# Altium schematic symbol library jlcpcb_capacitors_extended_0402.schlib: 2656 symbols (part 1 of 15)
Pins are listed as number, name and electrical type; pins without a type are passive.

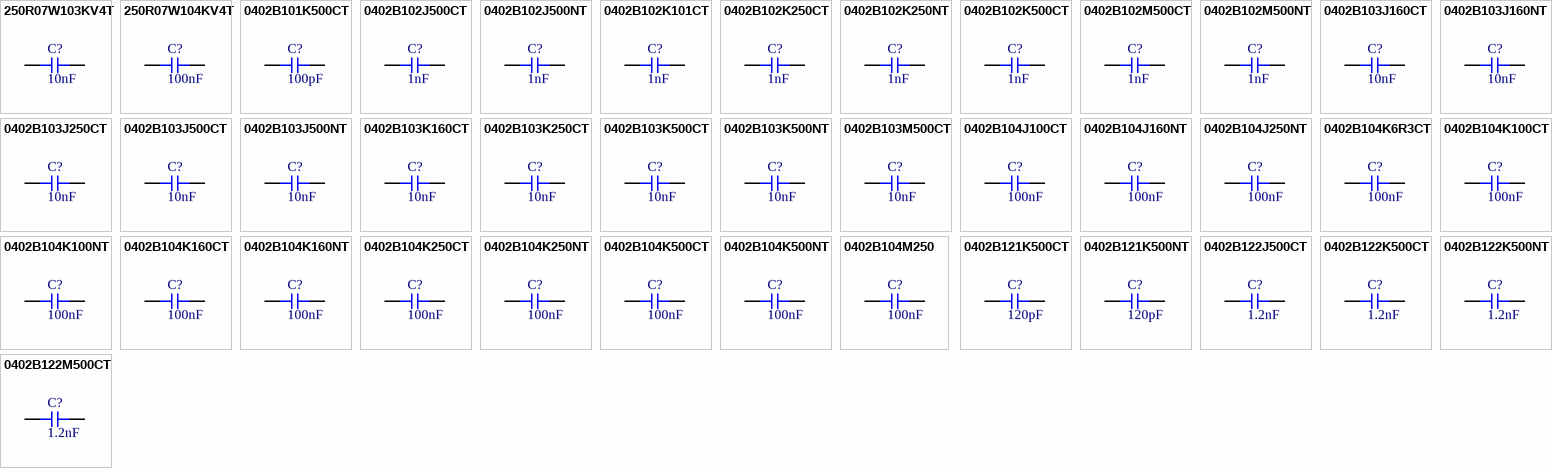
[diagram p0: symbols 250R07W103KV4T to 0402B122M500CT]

## 250R07W103KV4T
designator C?  Capacitance: 10nF  (hidden comment: *)
Capacitor, Ceramic (MLCC), 10nF, ±10%, 25V, X7R, ±10%, SMD 0402; Manufacturer: Johanson Dielectrics; Manufacturer Part Number: 250R07W103KV4T
footprint CAP-0402 (0402 (1005M) Capacitor)
pins: 1, 2

## 250R07W104KV4T
designator C?  Capacitance: 100nF  (hidden comment: *)
Capacitor, Ceramic (MLCC), 100nF, ±10%, 25V, X7R, ±10%, SMD 0402; Manufacturer: Johanson Dielectrics; Manufacturer Part Number: 250R07W104KV4T
footprint CAP-0402 (0402 (1005M) Capacitor)
pins: 1, 2

## 0402B101K500CT
designator C?  Capacitance: 100pF  (hidden comment: *)
Capacitor, Ceramic (MLCC), 100pF, ±10%, 50V, X7R, ±10%, SMD 0402; Manufacturer: Walsin Tech Corp; Manufacturer Part Number: 0402B101K500CT
footprint CAP-0402 (0402 (1005M) Capacitor)
pins: 1, 2

## 0402B102J500CT
designator C?  Capacitance: 1nF  (hidden comment: *)
Capacitor, Ceramic (MLCC), 1nF, ±5%, 50V, X7R, ±5%, SMD 0402; Manufacturer: Walsin Tech Corp; Manufacturer Part Number: 0402B102J500CT
footprint CAP-0402 (0402 (1005M) Capacitor)
pins: 1, 2

## 0402B102J500NT
designator C?  Capacitance: 1nF  (hidden comment: *)
Capacitor, Ceramic (MLCC), 1nF, ±5%, 50V, X7R, ±5%, SMD 0402; Manufacturer: FH(Guangdong Fenghua Advanced Tech); Manufacturer Part Number: 0402B102J500NT
footprint CAP-0402 (0402 (1005M) Capacitor)
pins: 1, 2

## 0402B102K101CT
designator C?  Capacitance: 1nF  (hidden comment: *)
Capacitor, Ceramic (MLCC), 1nF, ±10%, 100V, X7R, ±10%, SMD 0402; Manufacturer: Walsin Tech Corp; Manufacturer Part Number: 0402B102K101CT
footprint CAP-0402 (0402 (1005M) Capacitor)
pins: 1, 2

## 0402B102K250CT
designator C?  Capacitance: 1nF  (hidden comment: *)
Capacitor, Ceramic (MLCC), 1nF, ±10%, 25V, X7R, ±10%, SMD 0402; Manufacturer: Walsin Tech Corp; Manufacturer Part Number: 0402B102K250CT
footprint CAP-0402 (0402 (1005M) Capacitor)
pins: 1, 2

## 0402B102K250NT
designator C?  Capacitance: 1nF  (hidden comment: *)
Capacitor, Ceramic (MLCC), 1nF, ±10%, 25V, X7R, ±10%, SMD 0402; Manufacturer: FH(Guangdong Fenghua Advanced Tech); Manufacturer Part Number: 0402B102K250NT
footprint CAP-0402 (0402 (1005M) Capacitor)
pins: 1, 2

## 0402B102K500CT
designator C?  Capacitance: 1nF  (hidden comment: *)
Capacitor, Ceramic (MLCC), 1nF, ±10%, 50V, X7R, ±10%, SMD 0402; Manufacturer: Walsin Tech Corp; Manufacturer Part Number: 0402B102K500CT
footprint CAP-0402 (0402 (1005M) Capacitor)
pins: 1, 2

## 0402B102M500CT
designator C?  Capacitance: 1nF  (hidden comment: *)
Capacitor, Ceramic (MLCC), 1nF, ±20%, 50V, X7R, ±20%, SMD 0402; Manufacturer: Walsin Tech Corp; Manufacturer Part Number: 0402B102M500CT
footprint CAP-0402 (0402 (1005M) Capacitor)
pins: 1, 2

## 0402B102M500NT
designator C?  Capacitance: 1nF  (hidden comment: *)
Capacitor, Ceramic (MLCC), 1nF, ±20%, 50V, X7R, ±20%, SMD 0402; Manufacturer: FH(Guangdong Fenghua Advanced Tech); Manufacturer Part Number: 0402B102M500NT
footprint CAP-0402 (0402 (1005M) Capacitor)
pins: 1, 2

## 0402B103J160CT
designator C?  Capacitance: 10nF  (hidden comment: *)
Capacitor, Ceramic (MLCC), 10nF, ±5%, 16V, X7R, ±5%, SMD 0402; Manufacturer: Walsin Tech Corp; Manufacturer Part Number: 0402B103J160CT
footprint CAP-0402 (0402 (1005M) Capacitor)
pins: 1, 2

## 0402B103J160NT
designator C?  Capacitance: 10nF  (hidden comment: *)
Capacitor, Ceramic (MLCC), 10nF, ±5%, 16V, ±5%, SMD 0402; Manufacturer: FH (Guangdong Fenghua Advanced Tech); Manufacturer Part Number: 0402B103J160NT
footprint CAP-0402 (0402 (1005M) Capacitor)
pins: 1, 2

## 0402B103J250CT
designator C?  Capacitance: 10nF  (hidden comment: *)
Capacitor, Ceramic (MLCC), 10nF, ±5%, 25V, X7R, ±5%, SMD 0402; Manufacturer: Walsin Tech Corp; Manufacturer Part Number: 0402B103J250CT
footprint CAP-0402 (0402 (1005M) Capacitor)
pins: 1, 2

## 0402B103J500CT
designator C?  Capacitance: 10nF  (hidden comment: *)
Capacitor, Ceramic (MLCC), 10nF, ±5%, 50V, X7R, ±5%, SMD 0402; Manufacturer: Walsin Tech Corp; Manufacturer Part Number: 0402B103J500CT
footprint CAP-0402 (0402 (1005M) Capacitor)
pins: 1, 2

## 0402B103J500NT
designator C?  Capacitance: 10nF  (hidden comment: *)
Capacitor, Ceramic (MLCC), 10nF, ±5%, 50V, ±5%, SMD 0402; Manufacturer: FH (Guangdong Fenghua Advanced Tech); Manufacturer Part Number: 0402B103J500NT
footprint CAP-0402 (0402 (1005M) Capacitor)
pins: 1, 2

## 0402B103K160CT
designator C?  Capacitance: 10nF  (hidden comment: *)
Capacitor, Ceramic (MLCC), 10nF, ±10%, 16V, X7R, ±10%, SMD 0402; Manufacturer: Walsin Tech Corp; Manufacturer Part Number: 0402B103K160CT
footprint CAP-0402 (0402 (1005M) Capacitor)
pins: 1, 2

## 0402B103K250CT
designator C?  Capacitance: 10nF  (hidden comment: *)
Capacitor, Ceramic (MLCC), 10nF, ±10%, 25V, X7R, ±10%, SMD 0402; Manufacturer: Walsin Tech Corp; Manufacturer Part Number: 0402B103K250CT
footprint CAP-0402 (0402 (1005M) Capacitor)
pins: 1, 2

## 0402B103K500CT
designator C?  Capacitance: 10nF  (hidden comment: *)
Capacitor, Ceramic (MLCC), 10nF, ±10%, 50V, X7R, ±10%, SMD 0402; Manufacturer: Walsin Tech Corp; Manufacturer Part Number: 0402B103K500CT
footprint CAP-0402 (0402 (1005M) Capacitor)
pins: 1, 2

## 0402B103K500NT
designator C?  Capacitance: 10nF  (hidden comment: *)
Capacitor, Ceramic (MLCC), 10nF, ±10%, 50V, X7R, ±10%, SMD 0402; Manufacturer: FH(Guangdong Fenghua Advanced Tech); Manufacturer Part Number: 0402B103K500NT
footprint CAP-0402 (0402 (1005M) Capacitor)
pins: 1, 2

## 0402B103M500CT
designator C?  Capacitance: 10nF  (hidden comment: *)
Capacitor, Ceramic (MLCC), 10nF, ±20%, 50V, X7R, ±20%, SMD 0402; Manufacturer: Walsin Tech Corp; Manufacturer Part Number: 0402B103M500CT
footprint CAP-0402 (0402 (1005M) Capacitor)
pins: 1, 2

## 0402B104J100CT
designator C?  Capacitance: 100nF  (hidden comment: *)
Capacitor, Ceramic (MLCC), 100nF, ±5%, 10V, X7R, ±5%, SMD 0402; Manufacturer: Walsin Tech Corp; Manufacturer Part Number: 0402B104J100CT
footprint CAP-0402 (0402 (1005M) Capacitor)
pins: 1, 2

## 0402B104J160NT
designator C?  Capacitance: 100nF  (hidden comment: *)
Capacitor, Ceramic (MLCC), 100nF, ±5%, 16V, X7R, ±5%, SMD 0402; Manufacturer: FH(Guangdong Fenghua Advanced Tech); Manufacturer Part Number: 0402B104J160NT
footprint CAP-0402 (0402 (1005M) Capacitor)
pins: 1, 2

## 0402B104J250NT
designator C?  Capacitance: 100nF  (hidden comment: *)
Capacitor, Ceramic (MLCC), 100nF, ±5%, 25V, X7R, ±5%, SMD 0402; Manufacturer: FH(Guangdong Fenghua Advanced Tech); Manufacturer Part Number: 0402B104J250NT
footprint CAP-0402 (0402 (1005M) Capacitor)
pins: 1, 2

## 0402B104K6R3CT
designator C?  Capacitance: 100nF  (hidden comment: *)
Capacitor, Ceramic (MLCC), 100nF, ±10%, 6.3V, X7R, ±10%, SMD 0402; Manufacturer: Walsin Tech Corp; Manufacturer Part Number: 0402B104K6R3CT
footprint CAP-0402 (0402 (1005M) Capacitor)
pins: 1, 2

## 0402B104K100CT
designator C?  Capacitance: 100nF  (hidden comment: *)
Capacitor, Ceramic (MLCC), 100nF, ±10%, 10V, X7R, ±10%, SMD 0402; Manufacturer: Walsin Tech Corp; Manufacturer Part Number: 0402B104K100CT
footprint CAP-0402 (0402 (1005M) Capacitor)
pins: 1, 2

## 0402B104K100NT
designator C?  Capacitance: 100nF  (hidden comment: *)
Capacitor, Ceramic (MLCC), 100nF, ±10%, 10V, X7R, ±10%, SMD 0402; Manufacturer: FH(Guangdong Fenghua Advanced Tech); Manufacturer Part Number: 0402B104K100NT
footprint CAP-0402 (0402 (1005M) Capacitor)
pins: 1, 2

## 0402B104K160CT
designator C?  Capacitance: 100nF  (hidden comment: *)
Capacitor, Ceramic (MLCC), 100nF, ±10%, 16V, X7R, ±10%, SMD 0402; Manufacturer: Walsin Tech Corp; Manufacturer Part Number: 0402B104K160CT
footprint CAP-0402 (0402 (1005M) Capacitor)
pins: 1, 2

## 0402B104K160NT
designator C?  Capacitance: 100nF  (hidden comment: *)
Capacitor, Ceramic (MLCC), 100nF, ±10%, 16V, X7R, ±10%, SMD 0402; Manufacturer: FH(Guangdong Fenghua Advanced Tech); Manufacturer Part Number: 0402B104K160NT
footprint CAP-0402 (0402 (1005M) Capacitor)
pins: 1, 2

## 0402B104K250CT
designator C?  Capacitance: 100nF  (hidden comment: *)
Capacitor, Ceramic (MLCC), 100nF, ±10%, 25V, X7R, ±10%, SMD 0402; Manufacturer: Walsin Tech Corp; Manufacturer Part Number: 0402B104K250CT
footprint CAP-0402 (0402 (1005M) Capacitor)
pins: 1, 2

## 0402B104K250NT
designator C?  Capacitance: 100nF  (hidden comment: *)
Capacitor, Ceramic (MLCC), 100nF, ±10%, 25V, X7R, ±10%, SMD 0402; Manufacturer: FH(Guangdong Fenghua Advanced Tech); Manufacturer Part Number: 0402B104K250NT
footprint CAP-0402 (0402 (1005M) Capacitor)
pins: 1, 2

## 0402B104K500CT
designator C?  Capacitance: 100nF  (hidden comment: *)
Capacitor, Ceramic (MLCC), 100nF, ±10%, 50V, X7R, ±10%, SMD 0402; Manufacturer: Walsin Tech Corp; Manufacturer Part Number: 0402B104K500CT
footprint CAP-0402 (0402 (1005M) Capacitor)
pins: 1, 2

## 0402B104K500NT
designator C?  Capacitance: 100nF  (hidden comment: *)
Capacitor, Ceramic (MLCC), 100nF, ±10%, 50V, X7R, ±10%, SMD 0402; Manufacturer: FH(Guangdong Fenghua Advanced Tech); Manufacturer Part Number: 0402B104K500NT
footprint CAP-0402 (0402 (1005M) Capacitor)
pins: 1, 2

## 0402B104M250
designator C?  Capacitance: 100nF  (hidden comment: *)
Capacitor, Ceramic (MLCC), 100nF, ±20%, 25V, X7R, ±20%, SMD 0402; Manufacturer: Walsin Tech Corp; Manufacturer Part Number: 0402B104M250
footprint CAP-0402 (0402 (1005M) Capacitor)
pins: 1, 2

## 0402B121K500CT
designator C?  Capacitance: 120pF  (hidden comment: *)
Capacitor, Ceramic (MLCC), 120pF, ±10%, 50V, X7R, ±10%, SMD 0402; Manufacturer: Walsin Tech Corp; Manufacturer Part Number: 0402B121K500CT
footprint CAP-0402 (0402 (1005M) Capacitor)
pins: 1, 2

## 0402B121K500NT
designator C?  Capacitance: 120pF  (hidden comment: *)
Capacitor, Ceramic (MLCC), 120pF, ±10%, 50V, X7R, ±10%, SMD 0402; Manufacturer: FH(Guangdong Fenghua Advanced Tech); Manufacturer Part Number: 0402B121K500NT
footprint CAP-0402 (0402 (1005M) Capacitor)
pins: 1, 2

## 0402B122J500CT
designator C?  Capacitance: 1.2nF  (hidden comment: *)
Capacitor, Ceramic (MLCC), 1.2nF, ±5%, 50V, X7R, ±5%, SMD 0402; Manufacturer: Walsin Tech Corp; Manufacturer Part Number: 0402B122J500CT
footprint CAP-0402 (0402 (1005M) Capacitor)
pins: 1, 2

## 0402B122K500CT
designator C?  Capacitance: 1.2nF  (hidden comment: *)
Capacitor, Ceramic (MLCC), 1.2nF, ±10%, 50V, X7R, ±10%, SMD 0402; Manufacturer: Walsin Tech Corp; Manufacturer Part Number: 0402B122K500CT
footprint CAP-0402 (0402 (1005M) Capacitor)
pins: 1, 2

## 0402B122K500NT
designator C?  Capacitance: 1.2nF  (hidden comment: *)
Capacitor, Ceramic (MLCC), 1.2nF, ±10%, 50V, X7R, ±10%, SMD 0402; Manufacturer: FH(Guangdong Fenghua Advanced Tech); Manufacturer Part Number: 0402B122K500NT
footprint CAP-0402 (0402 (1005M) Capacitor)
pins: 1, 2

## 0402B122M500CT
designator C?  Capacitance: 1.2nF  (hidden comment: *)
Capacitor, Ceramic (MLCC), 1.2nF, ±20%, 50V, X7R, ±20%, SMD 0402; Manufacturer: Walsin Tech Corp; Manufacturer Part Number: 0402B122M500CT
footprint CAP-0402 (0402 (1005M) Capacitor)
pins: 1, 2

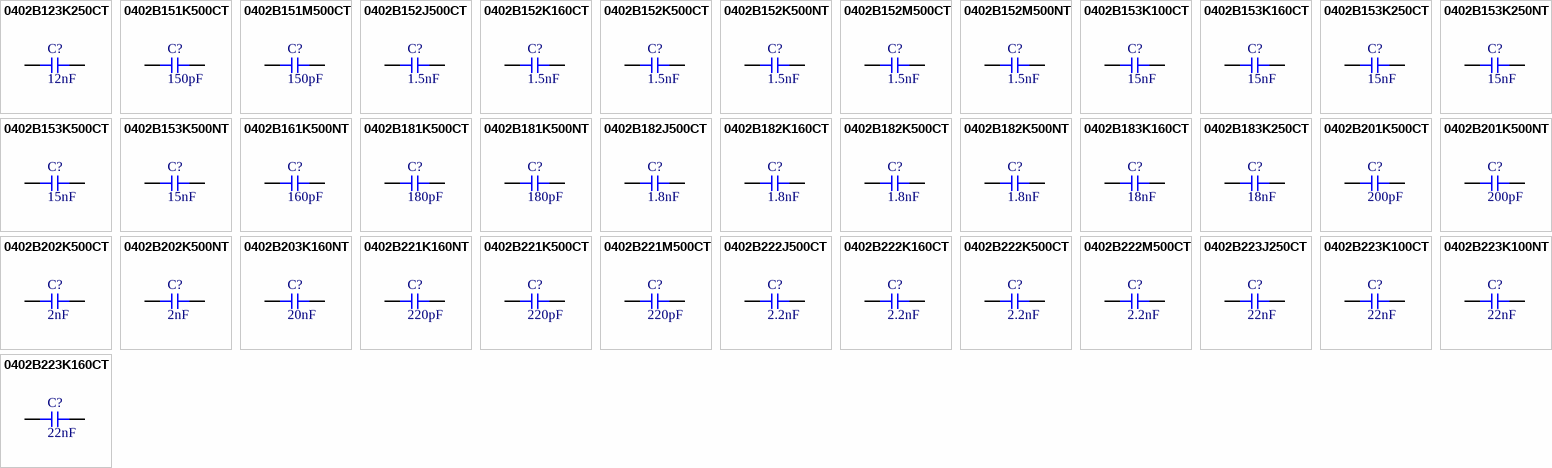
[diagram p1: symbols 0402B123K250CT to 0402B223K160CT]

## 0402B123K250CT
designator C?  Capacitance: 12nF  (hidden comment: *)
Capacitor, Ceramic (MLCC), 12nF, ±10%, 25V, X7R, ±10%, SMD 0402; Manufacturer: Walsin Tech Corp; Manufacturer Part Number: 0402B123K250CT
footprint CAP-0402 (0402 (1005M) Capacitor)
pins: 1, 2

## 0402B151K500CT
designator C?  Capacitance: 150pF  (hidden comment: *)
Capacitor, Ceramic (MLCC), 150pF, ±10%, 50V, X7R, ±10%, SMD 0402; Manufacturer: Walsin Tech Corp; Manufacturer Part Number: 0402B151K500CT
footprint CAP-0402 (0402 (1005M) Capacitor)
pins: 1, 2

## 0402B151M500CT
designator C?  Capacitance: 150pF  (hidden comment: *)
Capacitor, Ceramic (MLCC), 150pF, ±20%, 50V, X7R, ±20%, SMD 0402; Manufacturer: Walsin Tech Corp; Manufacturer Part Number: 0402B151M500CT
footprint CAP-0402 (0402 (1005M) Capacitor)
pins: 1, 2

## 0402B152J500CT
designator C?  Capacitance: 1.5nF  (hidden comment: *)
Capacitor, Ceramic (MLCC), 1.5nF, ±5%, 50V, X7R, ±5%, SMD 0402; Manufacturer: Walsin Tech Corp; Manufacturer Part Number: 0402B152J500CT
footprint CAP-0402 (0402 (1005M) Capacitor)
pins: 1, 2

## 0402B152K160CT
designator C?  Capacitance: 1.5nF  (hidden comment: *)
Capacitor, Ceramic (MLCC), 1.5nF, ±10%, 16V, X7R, ±10%, SMD 0402; Manufacturer: Walsin Tech Corp; Manufacturer Part Number: 0402B152K160CT
footprint CAP-0402 (0402 (1005M) Capacitor)
pins: 1, 2

## 0402B152K500CT
designator C?  Capacitance: 1.5nF  (hidden comment: *)
Capacitor, Ceramic (MLCC), 1.5nF, ±10%, 50V, X7R, ±10%, SMD 0402; Manufacturer: Walsin Tech Corp; Manufacturer Part Number: 0402B152K500CT
footprint CAP-0402 (0402 (1005M) Capacitor)
pins: 1, 2

## 0402B152K500NT
designator C?  Capacitance: 1.5nF  (hidden comment: *)
Capacitor, Ceramic (MLCC), 1.5nF, ±10%, 50V, X7R, ±10%, SMD 0402; Manufacturer: FH(Guangdong Fenghua Advanced Tech); Manufacturer Part Number: 0402B152K500NT
footprint CAP-0402 (0402 (1005M) Capacitor)
pins: 1, 2

## 0402B152M500CT
designator C?  Capacitance: 1.5nF  (hidden comment: *)
Capacitor, Ceramic (MLCC), 1.5nF, ±20%, 50V, X7R, ±20%, SMD 0402; Manufacturer: Walsin Tech Corp; Manufacturer Part Number: 0402B152M500CT
footprint CAP-0402 (0402 (1005M) Capacitor)
pins: 1, 2

## 0402B152M500NT
designator C?  Capacitance: 1.5nF  (hidden comment: *)
Capacitor, Ceramic (MLCC), 1.5nF, ±20%, 50V, X7R, ±20%, SMD 0402; Manufacturer: FH(Guangdong Fenghua Advanced Tech); Manufacturer Part Number: 0402B152M500NT
footprint CAP-0402 (0402 (1005M) Capacitor)
pins: 1, 2

## 0402B153K100CT
designator C?  Capacitance: 15nF  (hidden comment: *)
Capacitor, Ceramic (MLCC), 15nF, ±10%, 10V, X7R, ±10%, SMD 0402; Manufacturer: Walsin Tech Corp; Manufacturer Part Number: 0402B153K100CT
footprint CAP-0402 (0402 (1005M) Capacitor)
pins: 1, 2

## 0402B153K160CT
designator C?  Capacitance: 15nF  (hidden comment: *)
Capacitor, Ceramic (MLCC), 15nF, ±10%, 16V, X7R, ±10%, SMD 0402; Manufacturer: Walsin Tech Corp; Manufacturer Part Number: 0402B153K160CT
footprint CAP-0402 (0402 (1005M) Capacitor)
pins: 1, 2

## 0402B153K250CT
designator C?  Capacitance: 15nF  (hidden comment: *)
Capacitor, Ceramic (MLCC), 15nF, ±10%, 25V, X7R, ±10%, SMD 0402; Manufacturer: Walsin Tech Corp; Manufacturer Part Number: 0402B153K250CT
footprint CAP-0402 (0402 (1005M) Capacitor)
pins: 1, 2

## 0402B153K250NT
designator C?  Capacitance: 15nF  (hidden comment: *)
Capacitor, Ceramic (MLCC), 15nF, ±10%, 25V, X7R, ±10%, SMD 0402; Manufacturer: FH(Guangdong Fenghua Advanced Tech); Manufacturer Part Number: 0402B153K250NT
footprint CAP-0402 (0402 (1005M) Capacitor)
pins: 1, 2

## 0402B153K500CT
designator C?  Capacitance: 15nF  (hidden comment: *)
Capacitor, Ceramic (MLCC), 15nF, ±10%, 50V, X7R, ±10%, SMD 0402; Manufacturer: Walsin Tech Corp; Manufacturer Part Number: 0402B153K500CT
footprint CAP-0402 (0402 (1005M) Capacitor)
pins: 1, 2

## 0402B153K500NT
designator C?  Capacitance: 15nF  (hidden comment: *)
Capacitor, Ceramic (MLCC), 15nF, ±10%, 50V, X7R, ±10%, SMD 0402; Manufacturer: FH(Guangdong Fenghua Advanced Tech); Manufacturer Part Number: 0402B153K500NT
footprint CAP-0402 (0402 (1005M) Capacitor)
pins: 1, 2

## 0402B161K500NT
designator C?  Capacitance: 160pF  (hidden comment: *)
Capacitor, Ceramic (MLCC), 160pF, ±10%, 50V, X7R, ±10%, SMD 0402; Manufacturer: FH(Guangdong Fenghua Advanced Tech); Manufacturer Part Number: 0402B161K500NT
footprint CAP-0402 (0402 (1005M) Capacitor)
pins: 1, 2

## 0402B181K500CT
designator C?  Capacitance: 180pF  (hidden comment: *)
Capacitor, Ceramic (MLCC), 180pF, ±10%, 50V, X7R, ±10%, SMD 0402; Manufacturer: Walsin Tech Corp; Manufacturer Part Number: 0402B181K500CT
footprint CAP-0402 (0402 (1005M) Capacitor)
pins: 1, 2

## 0402B181K500NT
designator C?  Capacitance: 180pF  (hidden comment: *)
Capacitor, Ceramic (MLCC), 180pF, ±10%, 50V, X7R, ±10%, SMD 0402; Manufacturer: FH(Guangdong Fenghua Advanced Tech); Manufacturer Part Number: 0402B181K500NT
footprint CAP-0402 (0402 (1005M) Capacitor)
pins: 1, 2

## 0402B182J500CT
designator C?  Capacitance: 1.8nF  (hidden comment: *)
Capacitor, Ceramic (MLCC), 1.8nF, ±5%, 50V, X7R, ±5%, SMD 0402; Manufacturer: Walsin Tech Corp; Manufacturer Part Number: 0402B182J500CT
footprint CAP-0402 (0402 (1005M) Capacitor)
pins: 1, 2

## 0402B182K160CT
designator C?  Capacitance: 1.8nF  (hidden comment: *)
Capacitor, Ceramic (MLCC), 1.8nF, ±10%, 16V, X7R, ±10%, SMD 0402; Manufacturer: Walsin Tech Corp; Manufacturer Part Number: 0402B182K160CT
footprint CAP-0402 (0402 (1005M) Capacitor)
pins: 1, 2

## 0402B182K500CT
designator C?  Capacitance: 1.8nF  (hidden comment: *)
Capacitor, Ceramic (MLCC), 1.8nF, ±10%, 50V, X7R, ±10%, SMD 0402; Manufacturer: Walsin Tech Corp; Manufacturer Part Number: 0402B182K500CT
footprint CAP-0402 (0402 (1005M) Capacitor)
pins: 1, 2

## 0402B182K500NT
designator C?  Capacitance: 1.8nF  (hidden comment: *)
Capacitor, Ceramic (MLCC), 1.8nF, ±10%, 50V, X7R, ±10%, SMD 0402; Manufacturer: FH(Guangdong Fenghua Advanced Tech); Manufacturer Part Number: 0402B182K500NT
footprint CAP-0402 (0402 (1005M) Capacitor)
pins: 1, 2

## 0402B183K160CT
designator C?  Capacitance: 18nF  (hidden comment: *)
Capacitor, Ceramic (MLCC), 18nF, ±10%, 16V, X7R, ±10%, SMD 0402; Manufacturer: Walsin Tech Corp; Manufacturer Part Number: 0402B183K160CT
footprint CAP-0402 (0402 (1005M) Capacitor)
pins: 1, 2

## 0402B183K250CT
designator C?  Capacitance: 18nF  (hidden comment: *)
Capacitor, Ceramic (MLCC), 18nF, ±10%, 25V, X7R, ±10%, SMD 0402; Manufacturer: Walsin Tech Corp; Manufacturer Part Number: 0402B183K250CT
footprint CAP-0402 (0402 (1005M) Capacitor)
pins: 1, 2

## 0402B201K500CT
designator C?  Capacitance: 200pF  (hidden comment: *)
Capacitor, Ceramic (MLCC), 200pF, ±10%, 50V, X7R, ±10%, SMD 0402; Manufacturer: Walsin Tech Corp; Manufacturer Part Number: 0402B201K500CT
footprint CAP-0402 (0402 (1005M) Capacitor)
pins: 1, 2

## 0402B201K500NT
designator C?  Capacitance: 200pF  (hidden comment: *)
Capacitor, Ceramic (MLCC), 200pF, ±10%, 50V, X7R, ±10%, SMD 0402; Manufacturer: FH(Guangdong Fenghua Advanced Tech); Manufacturer Part Number: 0402B201K500NT
footprint CAP-0402 (0402 (1005M) Capacitor)
pins: 1, 2

## 0402B202K500CT
designator C?  Capacitance: 2nF  (hidden comment: *)
Capacitor, Ceramic (MLCC), 2nF, ±10%, 50V, X7R, ±10%, SMD 0402; Manufacturer: Walsin Tech Corp; Manufacturer Part Number: 0402B202K500CT
footprint CAP-0402 (0402 (1005M) Capacitor)
pins: 1, 2

## 0402B202K500NT
designator C?  Capacitance: 2nF  (hidden comment: *)
Capacitor, Ceramic (MLCC), 2nF, ±10%, 50V, ±10%, SMD 0402; Manufacturer: FH(Guangdong Fenghua Advanced Tech); Manufacturer Part Number: 0402B202K500NT
footprint CAP-0402 (0402 (1005M) Capacitor)
pins: 1, 2

## 0402B203K160NT
designator C?  Capacitance: 20nF  (hidden comment: *)
Capacitor, Ceramic (MLCC), 20nF, ±10%, 16V, ±10%, SMD 0402; Manufacturer: FH(Guangdong Fenghua Advanced Tech); Manufacturer Part Number: 0402B203K160NT
footprint CAP-0402 (0402 (1005M) Capacitor)
pins: 1, 2

## 0402B221K160NT
designator C?  Capacitance: 220pF  (hidden comment: *)
Capacitor, Ceramic (MLCC), 220pF, ±10%, 16V, X7R, ±10%, SMD 0402; Manufacturer: FH(Guangdong Fenghua Advanced Tech); Manufacturer Part Number: 0402B221K160NT
footprint CAP-0402 (0402 (1005M) Capacitor)
pins: 1, 2

## 0402B221K500CT
designator C?  Capacitance: 220pF  (hidden comment: *)
Capacitor, Ceramic (MLCC), 220pF, ±10%, 50V, X7R, ±10%, SMD 0402; Manufacturer: Walsin Tech Corp; Manufacturer Part Number: 0402B221K500CT
footprint CAP-0402 (0402 (1005M) Capacitor)
pins: 1, 2

## 0402B221M500CT
designator C?  Capacitance: 220pF  (hidden comment: *)
Capacitor, Ceramic (MLCC), 220pF, ±20%, 50V, X7R, ±20%, SMD 0402; Manufacturer: Walsin Tech Corp; Manufacturer Part Number: 0402B221M500CT
footprint CAP-0402 (0402 (1005M) Capacitor)
pins: 1, 2

## 0402B222J500CT
designator C?  Capacitance: 2.2nF  (hidden comment: *)
Capacitor, Ceramic (MLCC), 2.2nF, ±5%, 50V, X7R, ±5%, SMD 0402; Manufacturer: Walsin Tech Corp; Manufacturer Part Number: 0402B222J500CT
footprint CAP-0402 (0402 (1005M) Capacitor)
pins: 1, 2

## 0402B222K160CT
designator C?  Capacitance: 2.2nF  (hidden comment: *)
Capacitor, Ceramic (MLCC), 2.2nF, ±10%, 16V, X7R, ±10%, SMD 0402; Manufacturer: Walsin Tech Corp; Manufacturer Part Number: 0402B222K160CT
footprint CAP-0402 (0402 (1005M) Capacitor)
pins: 1, 2

## 0402B222K500CT
designator C?  Capacitance: 2.2nF  (hidden comment: *)
Capacitor, Ceramic (MLCC), 2.2nF, ±10%, 50V, X7R, ±10%, SMD 0402; Manufacturer: Walsin Tech Corp; Manufacturer Part Number: 0402B222K500CT
footprint CAP-0402 (0402 (1005M) Capacitor)
pins: 1, 2

## 0402B222M500CT
designator C?  Capacitance: 2.2nF  (hidden comment: *)
Capacitor, Ceramic (MLCC), 2.2nF, ±20%, 50V, X7R, ±20%, SMD 0402; Manufacturer: Walsin Tech Corp; Manufacturer Part Number: 0402B222M500CT
footprint CAP-0402 (0402 (1005M) Capacitor)
pins: 1, 2

## 0402B223J250CT
designator C?  Capacitance: 22nF  (hidden comment: *)
Capacitor, Ceramic (MLCC), 22nF, ±5%, 25V, X7R, ±5%, SMD 0402; Manufacturer: Walsin Tech Corp; Manufacturer Part Number: 0402B223J250CT
footprint CAP-0402 (0402 (1005M) Capacitor)
pins: 1, 2

## 0402B223K100CT
designator C?  Capacitance: 22nF  (hidden comment: *)
Capacitor, Ceramic (MLCC), 22nF, ±10%, 10V, X7R, ±10%, SMD 0402; Manufacturer: Walsin Tech Corp; Manufacturer Part Number: 0402B223K100CT
footprint CAP-0402 (0402 (1005M) Capacitor)
pins: 1, 2

## 0402B223K100NT
designator C?  Capacitance: 22nF  (hidden comment: *)
Capacitor, Ceramic (MLCC), 22nF, ±10%, 10V, X7R, ±10%, SMD 0402; Manufacturer: FH(Guangdong Fenghua Advanced Tech); Manufacturer Part Number: 0402B223K100NT
footprint CAP-0402 (0402 (1005M) Capacitor)
pins: 1, 2

## 0402B223K160CT
designator C?  Capacitance: 22nF  (hidden comment: *)
Capacitor, Ceramic (MLCC), 22nF, ±10%, 16V, X7R, ±10%, SMD 0402; Manufacturer: Walsin Tech Corp; Manufacturer Part Number: 0402B223K160CT
footprint CAP-0402 (0402 (1005M) Capacitor)
pins: 1, 2

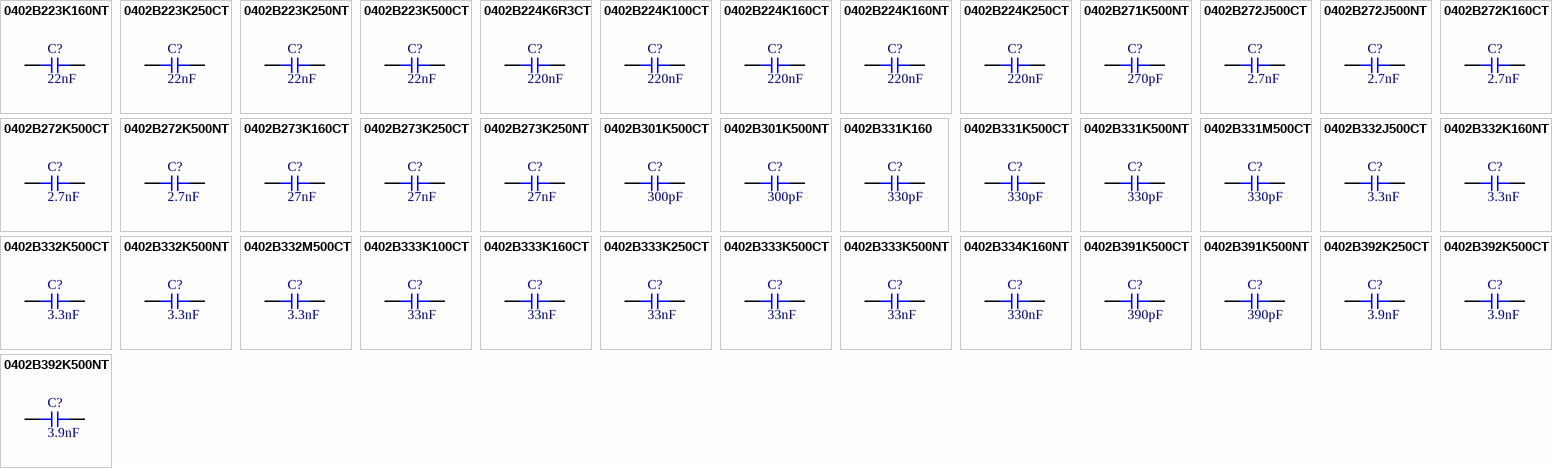
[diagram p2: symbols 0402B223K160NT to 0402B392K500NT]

## 0402B223K160NT
designator C?  Capacitance: 22nF  (hidden comment: *)
Capacitor, Ceramic (MLCC), 22nF, ±10%, 16V, X7R, ±10%, SMD 0402; Manufacturer: FH(Guangdong Fenghua Advanced Tech); Manufacturer Part Number: 0402B223K160NT
footprint CAP-0402 (0402 (1005M) Capacitor)
pins: 1, 2

## 0402B223K250CT
designator C?  Capacitance: 22nF  (hidden comment: *)
Capacitor, Ceramic (MLCC), 22nF, ±10%, 25V, X7R, ±10%, SMD 0402; Manufacturer: Walsin Tech Corp; Manufacturer Part Number: 0402B223K250CT
footprint CAP-0402 (0402 (1005M) Capacitor)
pins: 1, 2

## 0402B223K250NT
designator C?  Capacitance: 22nF  (hidden comment: *)
Capacitor, Ceramic (MLCC), 22nF, ±10%, 25V, X7R, ±10%, SMD 0402; Manufacturer: FH(Guangdong Fenghua Advanced Tech); Manufacturer Part Number: 0402B223K250NT
footprint CAP-0402 (0402 (1005M) Capacitor)
pins: 1, 2

## 0402B223K500CT
designator C?  Capacitance: 22nF  (hidden comment: *)
Capacitor, Ceramic (MLCC), 22nF, ±10%, 50V, X7R, ±10%, SMD 0402; Manufacturer: Walsin Tech Corp; Manufacturer Part Number: 0402B223K500CT
footprint CAP-0402 (0402 (1005M) Capacitor)
pins: 1, 2

## 0402B224K6R3CT
designator C?  Capacitance: 220nF  (hidden comment: *)
Capacitor, Ceramic (MLCC), 220nF, ±10%, 6.3V, X7R, ±10%, SMD 0402; Manufacturer: Walsin Tech Corp; Manufacturer Part Number: 0402B224K6R3CT
footprint CAP-0402 (0402 (1005M) Capacitor)
pins: 1, 2

## 0402B224K100CT
designator C?  Capacitance: 220nF  (hidden comment: *)
Capacitor, Ceramic (MLCC), 220nF, ±10%, 10V, X7R, ±10%, SMD 0402; Manufacturer: Walsin Tech Corp; Manufacturer Part Number: 0402B224K100CT
footprint CAP-0402 (0402 (1005M) Capacitor)
pins: 1, 2

## 0402B224K160CT
designator C?  Capacitance: 220nF  (hidden comment: *)
Capacitor, Ceramic (MLCC), 220nF, ±10%, 16V, X7R, ±10%, SMD 0402; Manufacturer: Walsin Tech Corp; Manufacturer Part Number: 0402B224K160CT
footprint CAP-0402 (0402 (1005M) Capacitor)
pins: 1, 2

## 0402B224K160NT
designator C?  Capacitance: 220nF  (hidden comment: *)
Capacitor, Ceramic (MLCC), 220nF, ±10%, 16V, X7R, ±10%, SMD 0402; Manufacturer: FH(Guangdong Fenghua Advanced Tech); Manufacturer Part Number: 0402B224K160NT
footprint CAP-0402 (0402 (1005M) Capacitor)
pins: 1, 2

## 0402B224K250CT
designator C?  Capacitance: 220nF  (hidden comment: *)
Capacitor, Ceramic (MLCC), 220nF, ±10%, 25V, X7R, ±10%, SMD 0402; Manufacturer: Walsin Tech Corp; Manufacturer Part Number: 0402B224K250CT
footprint CAP-0402 (0402 (1005M) Capacitor)
pins: 1, 2

## 0402B271K500NT
designator C?  Capacitance: 270pF  (hidden comment: *)
Capacitor, Ceramic (MLCC), 270pF, ±10%, 50V, X7R, ±10%, SMD 0402; Manufacturer: FH(Guangdong Fenghua Advanced Tech); Manufacturer Part Number: 0402B271K500NT
footprint CAP-0402 (0402 (1005M) Capacitor)
pins: 1, 2

## 0402B272J500CT
designator C?  Capacitance: 2.7nF  (hidden comment: *)
Capacitor, Ceramic (MLCC), 2.7nF, ±5%, 50V, X7R, ±5%, SMD 0402; Manufacturer: Walsin Tech Corp; Manufacturer Part Number: 0402B272J500CT
footprint CAP-0402 (0402 (1005M) Capacitor)
pins: 1, 2

## 0402B272J500NT
designator C?  Capacitance: 2.7nF  (hidden comment: *)
Capacitor, Ceramic (MLCC), 2.7nF, ±5%, 50V, X7R, ±5%, SMD 0402; Manufacturer: FH(Guangdong Fenghua Advanced Tech); Manufacturer Part Number: 0402B272J500NT
footprint CAP-0402 (0402 (1005M) Capacitor)
pins: 1, 2

## 0402B272K160CT
designator C?  Capacitance: 2.7nF  (hidden comment: *)
Capacitor, Ceramic (MLCC), 2.7nF, ±10%, 16V, X7R, ±10%, SMD 0402; Manufacturer: Walsin Tech Corp; Manufacturer Part Number: 0402B272K160CT
footprint CAP-0402 (0402 (1005M) Capacitor)
pins: 1, 2

## 0402B272K500CT
designator C?  Capacitance: 2.7nF  (hidden comment: *)
Capacitor, Ceramic (MLCC), 2.7nF, ±10%, 50V, X7R, ±10%, SMD 0402; Manufacturer: Walsin Tech Corp; Manufacturer Part Number: 0402B272K500CT
footprint CAP-0402 (0402 (1005M) Capacitor)
pins: 1, 2

## 0402B272K500NT
designator C?  Capacitance: 2.7nF  (hidden comment: *)
Capacitor, Ceramic (MLCC), 2.7nF, ±10%, 50V, X7R, ±10%, SMD 0402; Manufacturer: FH(Guangdong Fenghua Advanced Tech); Manufacturer Part Number: 0402B272K500NT
footprint CAP-0402 (0402 (1005M) Capacitor)
pins: 1, 2

## 0402B273K160CT
designator C?  Capacitance: 27nF  (hidden comment: *)
Capacitor, Ceramic (MLCC), 27nF, ±10%, 16V, X7R, ±10%, SMD 0402; Manufacturer: Walsin Tech Corp; Manufacturer Part Number: 0402B273K160CT
footprint CAP-0402 (0402 (1005M) Capacitor)
pins: 1, 2

## 0402B273K250CT
designator C?  Capacitance: 27nF  (hidden comment: *)
Capacitor, Ceramic (MLCC), 27nF, ±10%, 25V, X7R, ±10%, SMD 0402; Manufacturer: Walsin Tech Corp; Manufacturer Part Number: 0402B273K250CT
footprint CAP-0402 (0402 (1005M) Capacitor)
pins: 1, 2

## 0402B273K250NT
designator C?  Capacitance: 27nF  (hidden comment: *)
Capacitor, Ceramic (MLCC), 27nF, ±10%, 25V, X7R, ±10%, SMD 0402; Manufacturer: FH(Guangdong Fenghua Advanced Tech); Manufacturer Part Number: 0402B273K250NT
footprint CAP-0402 (0402 (1005M) Capacitor)
pins: 1, 2

## 0402B301K500CT
designator C?  Capacitance: 300pF  (hidden comment: *)
Capacitor, Ceramic (MLCC), 300pF, ±10%, 50V, X7R, ±10%, SMD 0402; Manufacturer: Walsin Tech Corp; Manufacturer Part Number: 0402B301K500CT
footprint CAP-0402 (0402 (1005M) Capacitor)
pins: 1, 2

## 0402B301K500NT
designator C?  Capacitance: 300pF  (hidden comment: *)
Capacitor, Ceramic (MLCC), 300pF, ±10%, 50V, X7R, ±10%, SMD 0402; Manufacturer: FH(Guangdong Fenghua Advanced Tech); Manufacturer Part Number: 0402B301K500NT
footprint CAP-0402 (0402 (1005M) Capacitor)
pins: 1, 2

## 0402B331K160
designator C?  Capacitance: 330pF  (hidden comment: *)
Capacitor, Ceramic (MLCC), 330pF, ±10%, 16V, X7R, ±10%, SMD 0402; Manufacturer: Walsin Tech Corp; Manufacturer Part Number: 0402B331K160
footprint CAP-0402 (0402 (1005M) Capacitor)
pins: 1, 2

## 0402B331K500CT
designator C?  Capacitance: 330pF  (hidden comment: *)
Capacitor, Ceramic (MLCC), 330pF, ±10%, 50V, X7R, ±10%, SMD 0402; Manufacturer: Walsin Tech Corp; Manufacturer Part Number: 0402B331K500CT
footprint CAP-0402 (0402 (1005M) Capacitor)
pins: 1, 2

## 0402B331K500NT
designator C?  Capacitance: 330pF  (hidden comment: *)
Capacitor, Ceramic (MLCC), 330pF, ±10%, 50V, X7R, ±10%, SMD 0402; Manufacturer: FH(Guangdong Fenghua Advanced Tech); Manufacturer Part Number: 0402B331K500NT
footprint CAP-0402 (0402 (1005M) Capacitor)
pins: 1, 2

## 0402B331M500CT
designator C?  Capacitance: 330pF  (hidden comment: *)
Capacitor, Ceramic (MLCC), 330pF, ±20%, 50V, X7R, ±20%, SMD 0402; Manufacturer: Walsin Tech Corp; Manufacturer Part Number: 0402B331M500CT
footprint CAP-0402 (0402 (1005M) Capacitor)
pins: 1, 2

## 0402B332J500CT
designator C?  Capacitance: 3.3nF  (hidden comment: *)
Capacitor, Ceramic (MLCC), 3.3nF, ±5%, 50V, X7R, ±5%, SMD 0402; Manufacturer: Walsin Tech Corp; Manufacturer Part Number: 0402B332J500CT
footprint CAP-0402 (0402 (1005M) Capacitor)
pins: 1, 2

## 0402B332K160NT
designator C?  Capacitance: 3.3nF  (hidden comment: *)
Capacitor, Ceramic (MLCC), 3.3nF, ±10%, 16V, X7R, ±10%, SMD 0402; Manufacturer: FH(Guangdong Fenghua Advanced Tech); Manufacturer Part Number: 0402B332K160NT
footprint CAP-0402 (0402 (1005M) Capacitor)
pins: 1, 2

## 0402B332K500CT
designator C?  Capacitance: 3.3nF  (hidden comment: *)
Capacitor, Ceramic (MLCC), 3.3nF, ±10%, 50V, X7R, ±10%, SMD 0402; Manufacturer: Walsin Tech Corp; Manufacturer Part Number: 0402B332K500CT
footprint CAP-0402 (0402 (1005M) Capacitor)
pins: 1, 2

## 0402B332K500NT
designator C?  Capacitance: 3.3nF  (hidden comment: *)
Capacitor, Ceramic (MLCC), 3.3nF, ±10%, 50V, X7R, ±10%, SMD 0402; Manufacturer: FH(Guangdong Fenghua Advanced Tech); Manufacturer Part Number: 0402B332K500NT
footprint CAP-0402 (0402 (1005M) Capacitor)
pins: 1, 2

## 0402B332M500CT
designator C?  Capacitance: 3.3nF  (hidden comment: *)
Capacitor, Ceramic (MLCC), 3.3nF, ±20%, 50V, X7R, ±20%, SMD 0402; Manufacturer: Walsin Tech Corp; Manufacturer Part Number: 0402B332M500CT
footprint CAP-0402 (0402 (1005M) Capacitor)
pins: 1, 2

## 0402B333K100CT
designator C?  Capacitance: 33nF  (hidden comment: *)
Capacitor, Ceramic (MLCC), 33nF, ±10%, 10V, X7R, ±10%, SMD 0402; Manufacturer: Walsin Tech Corp; Manufacturer Part Number: 0402B333K100CT
footprint CAP-0402 (0402 (1005M) Capacitor)
pins: 1, 2

## 0402B333K160CT
designator C?  Capacitance: 33nF  (hidden comment: *)
Capacitor, Ceramic (MLCC), 33nF, ±10%, 16V, X7R, ±10%, SMD 0402; Manufacturer: Walsin Tech Corp; Manufacturer Part Number: 0402B333K160CT
footprint CAP-0402 (0402 (1005M) Capacitor)
pins: 1, 2

## 0402B333K250CT
designator C?  Capacitance: 33nF  (hidden comment: *)
Capacitor, Ceramic (MLCC), 33nF, ±10%, 25V, X7R, ±10%, SMD 0402; Manufacturer: Walsin Tech Corp; Manufacturer Part Number: 0402B333K250CT
footprint CAP-0402 (0402 (1005M) Capacitor)
pins: 1, 2

## 0402B333K500CT
designator C?  Capacitance: 33nF  (hidden comment: *)
Capacitor, Ceramic (MLCC), 33nF, ±10%, 50V, X7R, ±10%, SMD 0402; Manufacturer: Walsin Tech Corp; Manufacturer Part Number: 0402B333K500CT
footprint CAP-0402 (0402 (1005M) Capacitor)
pins: 1, 2

## 0402B333K500NT
designator C?  Capacitance: 33nF  (hidden comment: *)
Capacitor, Ceramic (MLCC), 33nF, ±10%, 50V, X7R, ±10%, SMD 0402; Manufacturer: FH(Guangdong Fenghua Advanced Tech); Manufacturer Part Number: 0402B333K500NT
footprint CAP-0402 (0402 (1005M) Capacitor)
pins: 1, 2

## 0402B334K160NT
designator C?  Capacitance: 330nF  (hidden comment: *)
Capacitor, Ceramic (MLCC), 330nF, ±10%, 16V, X7R, ±10%, SMD 0402; Manufacturer: FH(Guangdong Fenghua Advanced Tech); Manufacturer Part Number: 0402B334K160NT
footprint CAP-0402 (0402 (1005M) Capacitor)
pins: 1, 2

## 0402B391K500CT
designator C?  Capacitance: 390pF  (hidden comment: *)
Capacitor, Ceramic (MLCC), 390pF, ±10%, 50V, X7R, ±10%, SMD 0402; Manufacturer: Walsin Tech Corp; Manufacturer Part Number: 0402B391K500CT
footprint CAP-0402 (0402 (1005M) Capacitor)
pins: 1, 2

## 0402B391K500NT
designator C?  Capacitance: 390pF  (hidden comment: *)
Capacitor, Ceramic (MLCC), 390pF, ±10%, 50V, X7R, ±10%, SMD 0402; Manufacturer: FH(Guangdong Fenghua Advanced Tech); Manufacturer Part Number: 0402B391K500NT
footprint CAP-0402 (0402 (1005M) Capacitor)
pins: 1, 2

## 0402B392K250CT
designator C?  Capacitance: 3.9nF  (hidden comment: *)
Capacitor, Ceramic (MLCC), 3.9nF, ±10%, 25V, X7R, ±10%, SMD 0402; Manufacturer: Walsin Tech Corp; Manufacturer Part Number: 0402B392K250CT
footprint CAP-0402 (0402 (1005M) Capacitor)
pins: 1, 2

## 0402B392K500CT
designator C?  Capacitance: 3.9nF  (hidden comment: *)
Capacitor, Ceramic (MLCC), 3.9nF, ±10%, 50V, X7R, ±10%, SMD 0402; Manufacturer: Walsin Tech Corp; Manufacturer Part Number: 0402B392K500CT
footprint CAP-0402 (0402 (1005M) Capacitor)
pins: 1, 2

## 0402B392K500NT
designator C?  Capacitance: 3.9nF  (hidden comment: *)
Capacitor, Ceramic (MLCC), 3.9nF, ±10%, 50V, X7R, ±10%, SMD 0402; Manufacturer: FH(Guangdong Fenghua Advanced Tech); Manufacturer Part Number: 0402B392K500NT
footprint CAP-0402 (0402 (1005M) Capacitor)
pins: 1, 2

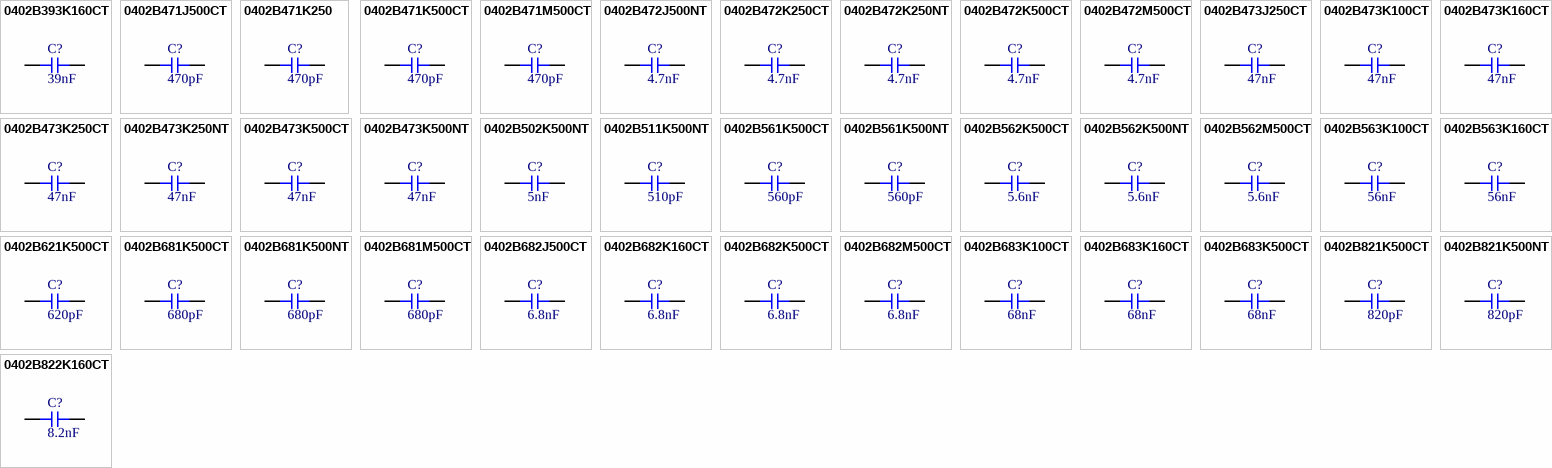
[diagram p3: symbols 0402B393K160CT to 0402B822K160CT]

## 0402B393K160CT
designator C?  Capacitance: 39nF  (hidden comment: *)
Capacitor, Ceramic (MLCC), 39nF, ±10%, 16V, X7R, ±10%, SMD 0402; Manufacturer: Walsin Tech Corp; Manufacturer Part Number: 0402B393K160CT
footprint CAP-0402 (0402 (1005M) Capacitor)
pins: 1, 2

## 0402B471J500CT
designator C?  Capacitance: 470pF  (hidden comment: *)
Capacitor, Ceramic (MLCC), 470pF, ±5%, 50V, X7R, ±5%, SMD 0402; Manufacturer: Walsin Tech Corp; Manufacturer Part Number: 0402B471J500CT
footprint CAP-0402 (0402 (1005M) Capacitor)
pins: 1, 2

## 0402B471K250
designator C?  Capacitance: 470pF  (hidden comment: *)
Capacitor, Ceramic (MLCC), 470pF, ±10%, 25V, X7R, ±10%, SMD 0402; Manufacturer: Walsin Tech Corp; Manufacturer Part Number: 0402B471K250
footprint CAP-0402 (0402 (1005M) Capacitor)
pins: 1, 2

## 0402B471K500CT
designator C?  Capacitance: 470pF  (hidden comment: *)
Capacitor, Ceramic (MLCC), 470pF, ±10%, 50V, X7R, ±10%, SMD 0402; Manufacturer: Walsin Tech Corp; Manufacturer Part Number: 0402B471K500CT
footprint CAP-0402 (0402 (1005M) Capacitor)
pins: 1, 2

## 0402B471M500CT
designator C?  Capacitance: 470pF  (hidden comment: *)
Capacitor, Ceramic (MLCC), 470pF, ±20%, 50V, X7R, ±20%, SMD 0402; Manufacturer: Walsin Tech Corp; Manufacturer Part Number: 0402B471M500CT
footprint CAP-0402 (0402 (1005M) Capacitor)
pins: 1, 2

## 0402B472J500NT
designator C?  Capacitance: 4.7nF  (hidden comment: *)
Capacitor, Ceramic (MLCC), 4.7nF, ±5%, 50V, X7R, ±5%, SMD 0402; Manufacturer: FH (Guangdong Fenghua Advanced Tech); Manufacturer Part Number: 0402B472J500NT
footprint CAP-0402 (0402 (1005M) Capacitor)
pins: 1, 2

## 0402B472K250CT
designator C?  Capacitance: 4.7nF  (hidden comment: *)
Capacitor, Ceramic (MLCC), 4.7nF, ±10%, 25V, X7R, ±10%, SMD 0402; Manufacturer: Walsin Tech Corp; Manufacturer Part Number: 0402B472K250CT
footprint CAP-0402 (0402 (1005M) Capacitor)
pins: 1, 2

## 0402B472K250NT
designator C?  Capacitance: 4.7nF  (hidden comment: *)
Capacitor, Ceramic (MLCC), 4.7nF, ±10%, 25V, X7R, ±10%, SMD 0402; Manufacturer: FH(Guangdong Fenghua Advanced Tech); Manufacturer Part Number: 0402B472K250NT
footprint CAP-0402 (0402 (1005M) Capacitor)
pins: 1, 2

## 0402B472K500CT
designator C?  Capacitance: 4.7nF  (hidden comment: *)
Capacitor, Ceramic (MLCC), 4.7nF, ±10%, 50V, X7R, ±10%, SMD 0402; Manufacturer: Walsin Tech Corp; Manufacturer Part Number: 0402B472K500CT
footprint CAP-0402 (0402 (1005M) Capacitor)
pins: 1, 2

## 0402B472M500CT
designator C?  Capacitance: 4.7nF  (hidden comment: *)
Capacitor, Ceramic (MLCC), 4.7nF, ±20%, 50V, X7R, ±20%, SMD 0402; Manufacturer: Walsin Tech Corp; Manufacturer Part Number: 0402B472M500CT
footprint CAP-0402 (0402 (1005M) Capacitor)
pins: 1, 2

## 0402B473J250CT
designator C?  Capacitance: 47nF  (hidden comment: *)
Capacitor, Ceramic (MLCC), 47nF, ±5%, 25V, X7R, ±5%, SMD 0402; Manufacturer: Walsin Tech Corp; Manufacturer Part Number: 0402B473J250CT
footprint CAP-0402 (0402 (1005M) Capacitor)
pins: 1, 2

## 0402B473K100CT
designator C?  Capacitance: 47nF  (hidden comment: *)
Capacitor, Ceramic (MLCC), 47nF, ±10%, 10V, X7R, ±10%, SMD 0402; Manufacturer: Walsin Tech Corp; Manufacturer Part Number: 0402B473K100CT
footprint CAP-0402 (0402 (1005M) Capacitor)
pins: 1, 2

## 0402B473K160CT
designator C?  Capacitance: 47nF  (hidden comment: *)
Capacitor, Ceramic (MLCC), 47nF, ±10%, 16V, X7R, ±10%, SMD 0402; Manufacturer: Walsin Tech Corp; Manufacturer Part Number: 0402B473K160CT
footprint CAP-0402 (0402 (1005M) Capacitor)
pins: 1, 2

## 0402B473K250CT
designator C?  Capacitance: 47nF  (hidden comment: *)
Capacitor, Ceramic (MLCC), 47nF, ±10%, 25V, X7R, ±10%, SMD 0402; Manufacturer: Walsin Tech Corp; Manufacturer Part Number: 0402B473K250CT
footprint CAP-0402 (0402 (1005M) Capacitor)
pins: 1, 2

## 0402B473K250NT
designator C?  Capacitance: 47nF  (hidden comment: *)
Capacitor, Ceramic (MLCC), 47nF, ±10%, 25V, X7R, ±10%, SMD 0402; Manufacturer: FH(Guangdong Fenghua Advanced Tech); Manufacturer Part Number: 0402B473K250NT
footprint CAP-0402 (0402 (1005M) Capacitor)
pins: 1, 2

## 0402B473K500CT
designator C?  Capacitance: 47nF  (hidden comment: *)
Capacitor, Ceramic (MLCC), 47nF, ±10%, 50V, X7R, ±10%, SMD 0402; Manufacturer: Walsin Tech Corp; Manufacturer Part Number: 0402B473K500CT
footprint CAP-0402 (0402 (1005M) Capacitor)
pins: 1, 2

## 0402B473K500NT
designator C?  Capacitance: 47nF  (hidden comment: *)
Capacitor, Ceramic (MLCC), 47nF, ±10%, 50V, X7R, ±10%, SMD 0402; Manufacturer: FH(Guangdong Fenghua Advanced Tech); Manufacturer Part Number: 0402B473K500NT
footprint CAP-0402 (0402 (1005M) Capacitor)
pins: 1, 2

## 0402B502K500NT
designator C?  Capacitance: 5nF  (hidden comment: *)
Capacitor, Ceramic (MLCC), 5nF, ±10%, 50V, ±10%, SMD 0402; Manufacturer: FH(Guangdong Fenghua Advanced Tech); Manufacturer Part Number: 0402B502K500NT
footprint CAP-0402 (0402 (1005M) Capacitor)
pins: 1, 2

## 0402B511K500NT
designator C?  Capacitance: 510pF  (hidden comment: *)
Capacitor, Ceramic (MLCC), 510pF, ±10%, 50V, X7R, ±10%, SMD 0402; Manufacturer: FH(Guangdong Fenghua Advanced Tech); Manufacturer Part Number: 0402B511K500NT
footprint CAP-0402 (0402 (1005M) Capacitor)
pins: 1, 2

## 0402B561K500CT
designator C?  Capacitance: 560pF  (hidden comment: *)
Capacitor, Ceramic (MLCC), 560pF, ±10%, 50V, X7R, ±10%, SMD 0402; Manufacturer: Walsin Tech Corp; Manufacturer Part Number: 0402B561K500CT
footprint CAP-0402 (0402 (1005M) Capacitor)
pins: 1, 2

## 0402B561K500NT
designator C?  Capacitance: 560pF  (hidden comment: *)
Capacitor, Ceramic (MLCC), 560pF, ±10%, 50V, X7R, ±10%, SMD 0402; Manufacturer: FH(Guangdong Fenghua Advanced Tech); Manufacturer Part Number: 0402B561K500NT
footprint CAP-0402 (0402 (1005M) Capacitor)
pins: 1, 2

## 0402B562K500CT
designator C?  Capacitance: 5.6nF  (hidden comment: *)
Capacitor, Ceramic (MLCC), 5.6nF, ±10%, 50V, X7R, ±10%, SMD 0402; Manufacturer: Walsin Tech Corp; Manufacturer Part Number: 0402B562K500CT
footprint CAP-0402 (0402 (1005M) Capacitor)
pins: 1, 2

## 0402B562K500NT
designator C?  Capacitance: 5.6nF  (hidden comment: *)
Capacitor, Ceramic (MLCC), 5.6nF, ±10%, 50V, X7R, ±10%, SMD 0402; Manufacturer: FH(Guangdong Fenghua Advanced Tech); Manufacturer Part Number: 0402B562K500NT
footprint CAP-0402 (0402 (1005M) Capacitor)
pins: 1, 2

## 0402B562M500CT
designator C?  Capacitance: 5.6nF  (hidden comment: *)
Capacitor, Ceramic (MLCC), 5.6nF, ±20%, 50V, X7R, ±20%, SMD 0402; Manufacturer: Walsin Tech Corp; Manufacturer Part Number: 0402B562M500CT
footprint CAP-0402 (0402 (1005M) Capacitor)
pins: 1, 2

## 0402B563K100CT
designator C?  Capacitance: 56nF  (hidden comment: *)
Capacitor, Ceramic (MLCC), 56nF, ±10%, 10V, X7R, ±10%, SMD 0402; Manufacturer: Walsin Tech Corp; Manufacturer Part Number: 0402B563K100CT
footprint CAP-0402 (0402 (1005M) Capacitor)
pins: 1, 2

## 0402B563K160CT
designator C?  Capacitance: 56nF  (hidden comment: *)
Capacitor, Ceramic (MLCC), 56nF, ±10%, 16V, X7R, ±10%, SMD 0402; Manufacturer: Walsin Tech Corp; Manufacturer Part Number: 0402B563K160CT
footprint CAP-0402 (0402 (1005M) Capacitor)
pins: 1, 2

## 0402B621K500CT
designator C?  Capacitance: 620pF  (hidden comment: *)
Capacitor, Ceramic (MLCC), 620pF, ±10%, 50V, X7R, ±10%, SMD 0402; Manufacturer: Walsin Tech Corp; Manufacturer Part Number: 0402B621K500CT
footprint CAP-0402 (0402 (1005M) Capacitor)
pins: 1, 2

## 0402B681K500CT
designator C?  Capacitance: 680pF  (hidden comment: *)
Capacitor, Ceramic (MLCC), 680pF, ±10%, 50V, X7R, ±10%, SMD 0402; Manufacturer: Walsin Tech Corp; Manufacturer Part Number: 0402B681K500CT
footprint CAP-0402 (0402 (1005M) Capacitor)
pins: 1, 2

## 0402B681K500NT
designator C?  Capacitance: 680pF  (hidden comment: *)
Capacitor, Ceramic (MLCC), 680pF, ±10%, 50V, X7R, ±10%, SMD 0402; Manufacturer: FH(Guangdong Fenghua Advanced Tech); Manufacturer Part Number: 0402B681K500NT
footprint CAP-0402 (0402 (1005M) Capacitor)
pins: 1, 2

## 0402B681M500CT
designator C?  Capacitance: 680pF  (hidden comment: *)
Capacitor, Ceramic (MLCC), 680pF, ±20%, 50V, X7R, ±20%, SMD 0402; Manufacturer: Walsin Tech Corp; Manufacturer Part Number: 0402B681M500CT
footprint CAP-0402 (0402 (1005M) Capacitor)
pins: 1, 2

## 0402B682J500CT
designator C?  Capacitance: 6.8nF  (hidden comment: *)
Capacitor, Ceramic (MLCC), 6.8nF, ±5%, 50V, X7R, ±5%, SMD 0402; Manufacturer: Walsin Tech Corp; Manufacturer Part Number: 0402B682J500CT
footprint CAP-0402 (0402 (1005M) Capacitor)
pins: 1, 2

## 0402B682K160CT
designator C?  Capacitance: 6.8nF  (hidden comment: *)
Capacitor, Ceramic (MLCC), 6.8nF, ±10%, 16V, X7R, ±10%, SMD 0402; Manufacturer: Walsin Tech Corp; Manufacturer Part Number: 0402B682K160CT
footprint CAP-0402 (0402 (1005M) Capacitor)
pins: 1, 2

## 0402B682K500CT
designator C?  Capacitance: 6.8nF  (hidden comment: *)
Capacitor, Ceramic (MLCC), 6.8nF, ±10%, 50V, X7R, ±10%, SMD 0402; Manufacturer: Walsin Tech Corp; Manufacturer Part Number: 0402B682K500CT
footprint CAP-0402 (0402 (1005M) Capacitor)
pins: 1, 2

## 0402B682M500CT
designator C?  Capacitance: 6.8nF  (hidden comment: *)
Capacitor, Ceramic (MLCC), 6.8nF, ±20%, 50V, X7R, ±20%, SMD 0402; Manufacturer: Walsin Tech Corp; Manufacturer Part Number: 0402B682M500CT
footprint CAP-0402 (0402 (1005M) Capacitor)
pins: 1, 2

## 0402B683K100CT
designator C?  Capacitance: 68nF  (hidden comment: *)
Capacitor, Ceramic (MLCC), 68nF, ±10%, 10V, X7R, ±10%, SMD 0402; Manufacturer: Walsin Tech Corp; Manufacturer Part Number: 0402B683K100CT
footprint CAP-0402 (0402 (1005M) Capacitor)
pins: 1, 2

## 0402B683K160CT
designator C?  Capacitance: 68nF  (hidden comment: *)
Capacitor, Ceramic (MLCC), 68nF, ±10%, 16V, X7R, ±10%, SMD 0402; Manufacturer: Walsin Tech Corp; Manufacturer Part Number: 0402B683K160CT
footprint CAP-0402 (0402 (1005M) Capacitor)
pins: 1, 2

## 0402B683K500CT
designator C?  Capacitance: 68nF  (hidden comment: *)
Capacitor, Ceramic (MLCC), 68nF, ±10%, 50V, X7R, ±10%, SMD 0402; Manufacturer: Walsin Tech Corp; Manufacturer Part Number: 0402B683K500CT
footprint CAP-0402 (0402 (1005M) Capacitor)
pins: 1, 2

## 0402B821K500CT
designator C?  Capacitance: 820pF  (hidden comment: *)
Capacitor, Ceramic (MLCC), 820pF, ±10%, 50V, X7R, ±10%, SMD 0402; Manufacturer: Walsin Tech Corp; Manufacturer Part Number: 0402B821K500CT
footprint CAP-0402 (0402 (1005M) Capacitor)
pins: 1, 2

## 0402B821K500NT
designator C?  Capacitance: 820pF  (hidden comment: *)
Capacitor, Ceramic (MLCC), 820pF, ±10%, 50V, X7R, ±10%, SMD 0402; Manufacturer: FH(Guangdong Fenghua Advanced Tech); Manufacturer Part Number: 0402B821K500NT
footprint CAP-0402 (0402 (1005M) Capacitor)
pins: 1, 2

## 0402B822K160CT
designator C?  Capacitance: 8.2nF  (hidden comment: *)
Capacitor, Ceramic (MLCC), 8.2nF, ±10%, 16V, X7R, ±10%, SMD 0402; Manufacturer: Walsin Tech Corp; Manufacturer Part Number: 0402B822K160CT
footprint CAP-0402 (0402 (1005M) Capacitor)
pins: 1, 2

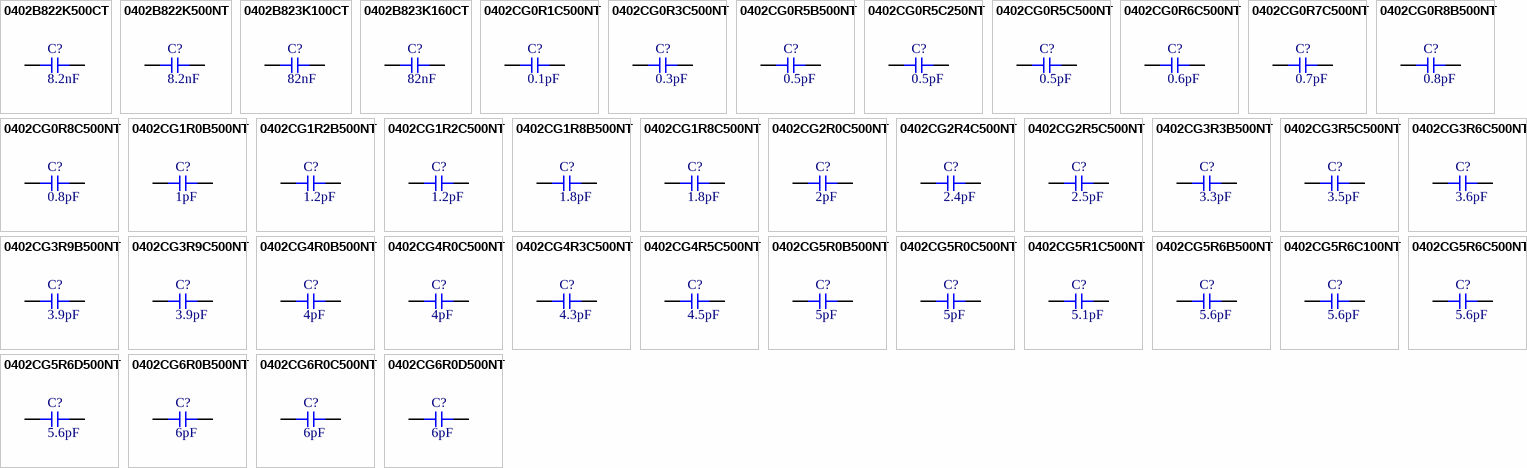
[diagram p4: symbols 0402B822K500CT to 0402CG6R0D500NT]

## 0402B822K500CT
designator C?  Capacitance: 8.2nF  (hidden comment: *)
Capacitor, Ceramic (MLCC), 8.2nF, ±10%, 50V, X7R, ±10%, SMD 0402; Manufacturer: Walsin Tech Corp; Manufacturer Part Number: 0402B822K500CT
footprint CAP-0402 (0402 (1005M) Capacitor)
pins: 1, 2

## 0402B822K500NT
designator C?  Capacitance: 8.2nF  (hidden comment: *)
Capacitor, Ceramic (MLCC), 8.2nF, ±10%, 50V, X7R, ±10%, SMD 0402; Manufacturer: FH(Guangdong Fenghua Advanced Tech); Manufacturer Part Number: 0402B822K500NT
footprint CAP-0402 (0402 (1005M) Capacitor)
pins: 1, 2

## 0402B823K100CT
designator C?  Capacitance: 82nF  (hidden comment: *)
Capacitor, Ceramic (MLCC), 82nF, ±10%, 10V, X7R, ±10%, SMD 0402; Manufacturer: Walsin Tech Corp; Manufacturer Part Number: 0402B823K100CT
footprint CAP-0402 (0402 (1005M) Capacitor)
pins: 1, 2

## 0402B823K160CT
designator C?  Capacitance: 82nF  (hidden comment: *)
Capacitor, Ceramic (MLCC), 82nF, ±10%, 16V, X7R, ±10%, SMD 0402; Manufacturer: Walsin Tech Corp; Manufacturer Part Number: 0402B823K160CT
footprint CAP-0402 (0402 (1005M) Capacitor)
pins: 1, 2

## 0402CG0R1C500NT
designator C?  Capacitance: 0.1pF  (hidden comment: *)
Capacitor, Ceramic (MLCC), 0.1pF, ±0.25pF, 50V, C0G, ±0.25pF, SMD 0402; Manufacturer: FH(Guangdong Fenghua Advanced Tech); Manufacturer Part Number: 0402CG0R1C500NT
footprint CAP-0402 (0402 (1005M) Capacitor)
pins: 1, 2

## 0402CG0R3C500NT
designator C?  Capacitance: 0.3pF  (hidden comment: *)
Capacitor, Ceramic (MLCC), 0.3pF, ±0.25pF, 50V, ±0.25pF, SMD 0402; Manufacturer: FH(Guangdong Fenghua Advanced Tech); Manufacturer Part Number: 0402CG0R3C500NT
footprint CAP-0402 (0402 (1005M) Capacitor)
pins: 1, 2

## 0402CG0R5B500NT
designator C?  Capacitance: 0.5pF  (hidden comment: *)
Capacitor, Ceramic (MLCC), 0.5pF, ±0.1pF, 50V, C0G, ±0.1pF, SMD 0402; Manufacturer: FH(Guangdong Fenghua Advanced Tech); Manufacturer Part Number: 0402CG0R5B500NT
footprint CAP-0402 (0402 (1005M) Capacitor)
pins: 1, 2

## 0402CG0R5C250NT
designator C?  Capacitance: 0.5pF  (hidden comment: *)
Capacitor, Ceramic (MLCC), 0.5pF, ±0.25pF, 25V, C0G, ±0.25pF, SMD 0402; Manufacturer: FH(Guangdong Fenghua Advanced Tech); Manufacturer Part Number: 0402CG0R5C250NT
footprint CAP-0402 (0402 (1005M) Capacitor)
pins: 1, 2

## 0402CG0R5C500NT
designator C?  Capacitance: 0.5pF  (hidden comment: *)
Capacitor, Ceramic (MLCC), 0.5pF, ±0.25pF, 50V, C0G, ±0.25pF, SMD 0402; Manufacturer: FH(Guangdong Fenghua Advanced Tech); Manufacturer Part Number: 0402CG0R5C500NT
footprint CAP-0402 (0402 (1005M) Capacitor)
pins: 1, 2

## 0402CG0R6C500NT
designator C?  Capacitance: 0.6pF  (hidden comment: *)
Capacitor, Ceramic (MLCC), 0.6pF, ±0.25pF, 50V, C0G, ±0.25pF, SMD 0402; Manufacturer: FH(Guangdong Fenghua Advanced Tech); Manufacturer Part Number: 0402CG0R6C500NT
footprint CAP-0402 (0402 (1005M) Capacitor)
pins: 1, 2

## 0402CG0R7C500NT
designator C?  Capacitance: 0.7pF  (hidden comment: *)
Capacitor, Ceramic (MLCC), 0.7pF, ±0.25pF, 50V, C0G, ±0.25pF, SMD 0402; Manufacturer: FH(Guangdong Fenghua Advanced Tech); Manufacturer Part Number: 0402CG0R7C500NT
footprint CAP-0402 (0402 (1005M) Capacitor)
pins: 1, 2

## 0402CG0R8B500NT
designator C?  Capacitance: 0.8pF  (hidden comment: *)
Capacitor, Ceramic (MLCC), 0.8pF, ±0.1pF, 50V, C0G, ±0.1pF, SMD 0402; Manufacturer: FH(Guangdong Fenghua Advanced Tech); Manufacturer Part Number: 0402CG0R8B500NT
footprint CAP-0402 (0402 (1005M) Capacitor)
pins: 1, 2

## 0402CG0R8C500NT
designator C?  Capacitance: 0.8pF  (hidden comment: *)
Capacitor, Ceramic (MLCC), 0.8pF, ±0.25pF, 50V, C0G, ±0.25pF, SMD 0402; Manufacturer: FH(Guangdong Fenghua Advanced Tech); Manufacturer Part Number: 0402CG0R8C500NT
footprint CAP-0402 (0402 (1005M) Capacitor)
pins: 1, 2

## 0402CG1R0B500NT
designator C?  Capacitance: 1pF  (hidden comment: *)
Capacitor, Ceramic (MLCC), 1pF, ±0.1pF, 50V, C0G, ±0.1pF, SMD 0402; Manufacturer: FH(Guangdong Fenghua Advanced Tech); Manufacturer Part Number: 0402CG1R0B500NT
footprint CAP-0402 (0402 (1005M) Capacitor)
pins: 1, 2

## 0402CG1R2B500NT
designator C?  Capacitance: 1.2pF  (hidden comment: *)
Capacitor, Ceramic (MLCC), 1.2pF, ±0.1pF, 50V, C0G, ±0.1pF, SMD 0402; Manufacturer: FH(Guangdong Fenghua Advanced Tech); Manufacturer Part Number: 0402CG1R2B500NT
footprint CAP-0402 (0402 (1005M) Capacitor)
pins: 1, 2

## 0402CG1R2C500NT
designator C?  Capacitance: 1.2pF  (hidden comment: *)
Capacitor, Ceramic (MLCC), 1.2pF, ±0.25pF, 50V, C0G, ±0.25pF, SMD 0402; Manufacturer: FH(Guangdong Fenghua Advanced Tech); Manufacturer Part Number: 0402CG1R2C500NT
footprint CAP-0402 (0402 (1005M) Capacitor)
pins: 1, 2

## 0402CG1R8B500NT
designator C?  Capacitance: 1.8pF  (hidden comment: *)
Capacitor, Ceramic (MLCC), 1.8pF, ±0.1pF, 50V, C0G, ±0.1pF, SMD 0402; Manufacturer: FH(Guangdong Fenghua Advanced Tech); Manufacturer Part Number: 0402CG1R8B500NT
footprint CAP-0402 (0402 (1005M) Capacitor)
pins: 1, 2

## 0402CG1R8C500NT
designator C?  Capacitance: 1.8pF  (hidden comment: *)
Capacitor, Ceramic (MLCC), 1.8pF, ±0.25pF, 50V, C0G, ±0.25pF, SMD 0402; Manufacturer: FH(Guangdong Fenghua Advanced Tech); Manufacturer Part Number: 0402CG1R8C500NT
footprint CAP-0402 (0402 (1005M) Capacitor)
pins: 1, 2

## 0402CG2R0C500NT
designator C?  Capacitance: 2pF  (hidden comment: *)
Capacitor, Ceramic (MLCC), 2pF, ±0.25pF, 50V, C0G, ±0.25pF, SMD 0402; Manufacturer: FH(Guangdong Fenghua Advanced Tech); Manufacturer Part Number: 0402CG2R0C500NT
footprint CAP-0402 (0402 (1005M) Capacitor)
pins: 1, 2

## 0402CG2R4C500NT
designator C?  Capacitance: 2.4pF  (hidden comment: *)
Capacitor, Ceramic (MLCC), 2.4pF, ±0.25pF, 50V, C0G, ±0.25pF, SMD 0402; Manufacturer: FH(Guangdong Fenghua Advanced Tech); Manufacturer Part Number: 0402CG2R4C500NT
footprint CAP-0402 (0402 (1005M) Capacitor)
pins: 1, 2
